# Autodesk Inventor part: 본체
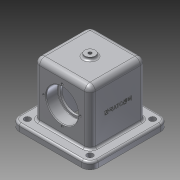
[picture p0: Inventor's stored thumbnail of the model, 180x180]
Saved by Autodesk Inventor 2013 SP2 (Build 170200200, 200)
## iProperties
Created: 2022-07
Part Number: 본체
Material: 알루미늄 6061
Document SubType Name: Modeling
Designer: i
Density: 2.71 g/cm^3
Mass: 1063.76 g
Surface Area: 721.846 cm^2
Volume: 392.531 cm^3
Author: i
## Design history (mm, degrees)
sketch "스케치1"
  geometry: L1 (58, 58)-(-58, 58); L2 (-58, 58)-(-58, -58); L3 (-58, -58)-(58, -58); L4 (58, -58)-(58, 58); L5 (58, 58)-(-58, -58); L6 (-58, 58)-(58, -58); 1 further point
  constraints: 12 end point, 2 midpoint, 2 parallel, 1 horizontal, 1 perpendicular
  dimensions: "d0" = 116 distance of L3.end L2.end; "d1" = 116 distance of L2.end L1.end
extrude "돌출1" new body sketch "스케치1" distance "d2" = 10; taper "d3" = 0 deg
sketch "스케치2"
  geometry: L1 (-41, -41)-(41, -41); L2 (41, -41)-(41, 41); L3 (41, 41)-(-41, 41); L4 (-41, 41)-(-41, -41); L5 (-41, -41)-(41, 41); L6 (41, -41)-(-41, 41); 1 further point
  constraints: 12 end point, 2 midpoint, 2 parallel, 1 horizontal, 1 perpendicular
  dimensions: "d4" = 82 distance of L3.end L2.end; "d5" = 82 distance of L2.end L1.end
extrude "돌출2" join sketch "스케치2" distance "d6" = 80; taper "d7" = 0 deg
sketch "스케치3"
  geometry: L1 (82, 0)-(0, 0) reference; L2 (82, 0)-(82, 80) reference; L3 (0, 80)-(82, 80) reference; L4 (0, 0)-(0, 80) reference; L5 (41, -10)-(41, 38); C1 r 23.5 at (41, 38)
  constraints: 2 end point, 1 centre point, 1 coincident, 1 parallel
  dimensions: "d8" = 48 distance of L5.start L5.end; "d9" = 47 diameter of C1
extrude "돌출3" cut sketch "스케치3" distance "d10" = 17; taper "d11" = 0 deg
sketch "스케치4"
  geometry: C1 r 23.5 at (0, 0) reference; C2 r 20 at (0, 0); 1 further point
  constraints: 1 centre point, 1 coincident
  dimensions: "d12" = 40 diameter of C2
sketch "스케치5"
  geometry: C1 r 23.5 at (41, 38) reference; C2 r 23.5 at (41, 38); 1 further point
  constraints: 1 centre point, 1 coincident
  dimensions: "d13" = 47 diameter of C2
extrude "돌출4" cut sketch "스케치5" distance "d14" = 17; taper "d15" = 0 deg
extrude "돌출5" cut sketch "스케치4" stored distance "d16" = 17; taper "d17" = 0 deg
sketch "스케치6"
  geometry: L1 (30, 21)-(-30, 21); L2 (-30, 21)-(-30, -21); L3 (-30, -21)-(30, -21); L4 (30, -21)-(30, 21); L5 (30, 21)-(-30, -21); L6 (-30, 21)-(30, -21); 1 further point
  constraints: 12 end point, 2 midpoint, 2 parallel, 1 horizontal, 1 perpendicular
  dimensions: "d18" = 60 distance of L3.end L2.end; "d19" = 42 distance of L2.end L1.end
extrude "돌출6" cut sketch "스케치6" distance "d20" = 80; taper "d21" = 0 deg
sketch "스케치7"
  geometry: L1 (0, 0)-(0, 80) reference; L2 (41, 38)-(41, 65); C1 r 23.5 at (41, 38) reference; 2 further points
  constraints: 2 end point, 1 coincident, 1 parallel
  dimensions: "d22" = 27 distance of L2.start L2.end
hole "구멍1" sketch "스케치7" at (41, 65) diameter "d23" = 3.242; stored, may be unused: countersink angle "d27" = 90 deg, drill point angle "d29" = 118 deg; dims "d24" = 8, "d25" = 4, "d26" = 2, "d28" = 10
sketch "스케치8"
  geometry: C1 r 7.5 at (0, 0); 1 further point
  constraints: 1 centre point, 1 coincident
  dimensions: "d33" = 15 diameter of C1
extrude "돌출7" join sketch "스케치8" distance "d34" = 4; taper "d35" = 0 deg
sketch "스케치9"
  geometry: C1 r 7.5 at (0, 0) reference; 1 further point
  constraints: 1 coincident
hole "구멍2" sketch "스케치9" at (0, 0) diameter "d36" = 4.917; stored, may be unused: countersink angle "d40" = 90 deg, drill point angle "d42" = 118 deg; dims "d37" = 14, "d38" = 4, "d39" = 2, "d41" = 10
fillet "모깎기1" dims "d43" = 0.6
chamfer "모따기1" distance "d44" = 1; stored, may be unused: second distance "d45" = 2, angle "d46" = 45 deg
fillet "모깎기2" dims "d47" = 3
fillet "모깎기3" dims "d48" = 8
fillet "모깎기4" dims "d49" = 8
fillet "모깎기5" dims "d50" = 3
fillet "모깎기6" dims "d51" = 12
fillet "모깎기7" dims "d52" = 3
sketch "스케치10"
  geometry: C1 r 4.5 at (-46, 46); A1 r 9 centre (-46, 46) between (-46, 55) and (-55, 46) reference; 1 further point
  constraints: 1 centre point, 1 coincident
  dimensions: "d53" = 9 diameter of C1
extrude "돌출8" cut sketch "스케치10" stored distance "d54" = 4; taper "d55" = 0 deg
fillet "모깎기8" dims "d59" = 3
fillet "모깎기9" dims "d60" = 3
sketch "스케치11"
  geometry: L1 (66, -69)-(0, -69) reference; L2 (-13, -82)-(79, -82) reference; 3 further points
  constraints: 1 midpoint, 1 vertical alignment, 1 other
  dimensions: "d61" = 48 distance from line of L2 point (33, -34)
feature "엠보싱1" sketch "스케치11" dims "d0" = 116, "d1" = 116, "d62" = 0.5, "d63" = 0
node "솔리드1"
pattern_circular "원형 패턴1" dims angle "d31" = 360 deg
mirror "대칭1"
pattern_circular "원형 패턴2" dims angle "d57" = 360 deg
node "투영된 루프1"
